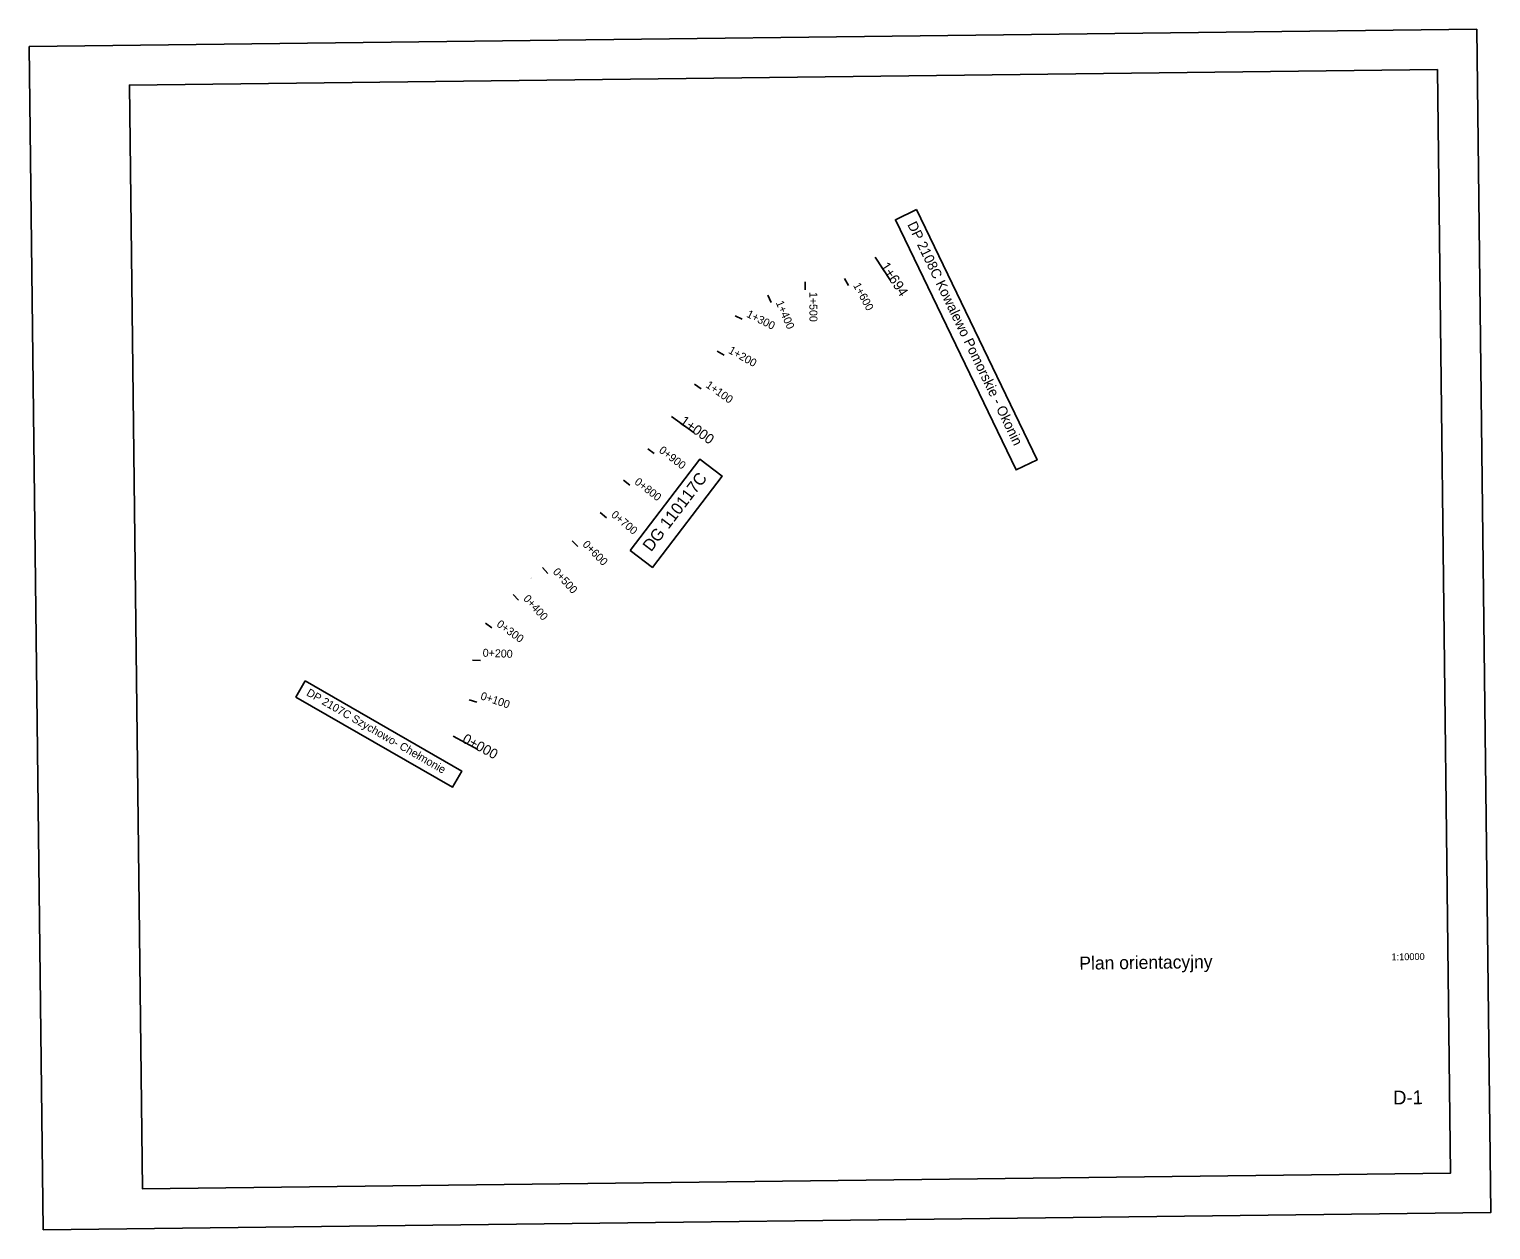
# Model space of a CAD drawing. Extents: x 6558557 to 6562223, y 5886898 to 5889911.
import ezdxf

# ---------------------------------------------------------------- set-up
doc = ezdxf.new("R2010")
doc.units = 0
for name, color, linetype in [('.opisy', 7, 'Continuous'), ('DRAFT_opis', 7, 'Continuous'), ('Level 1', 7, 'Continuous'), ('opis', 7, 'Continuous'), ('Plan proj opisy km', 7, 'Continuous')]:
    doc.layers.add(name, color=color, linetype=linetype)

msp = doc.modelspace()

# ---------------------------------------------------------------- linework, layer by layer
at = {"layer": '.opisy'}
for points in [[(6558557.1, 5889867.8), (6562188.2, 5889910.8), (6562223.3, 5886941), (6558592.3, 5886898)], [(6562089.4, 5889809.6), (6562122.1, 5887039.8), (6558841.1, 5887000.9), (6558808.3, 5889770.7)]]:
    msp.add_lwpolyline(points, close=True, dxfattribs=at)
at = {"layer": 'DRAFT_opis'}
for points in [[(6560782.6, 5889458), (6561085.3, 5888830), (6561032.8, 5888804.7), (6560730.1, 5889432.7)], [(6560064.7, 5888602.4), (6560239.5, 5888831.9), (6560295.1, 5888789.5), (6560120.4, 5888560.1)], [(6559249.3, 5888275.2), (6559642, 5888049), (6559618.7, 5888008.6), (6559226, 5888234.8)]]:
    msp.add_lwpolyline(points, close=True, dxfattribs=at)
at = {"layer": 'Plan proj opisy km'}
for points in [[(6560717.9, 5889279.9), (6560679.5, 5889338.4)], [(6560717.9, 5889279.9), (6560679.5, 5889338.4)], [(6560503.9, 5889256.5), (6560503.8, 5889276.5)], [(6560611.9, 5889267.8), (6560602.3, 5889285.4)], [(6560418.2, 5889225.1), (6560410.2, 5889243.4)], [(6560345.5, 5889182.9), (6560327.6, 5889191.8)], [(6560300, 5889092.8), (6560282.5, 5889102.6)], [(6560242.4, 5889008.5), (6560226.1, 5889020.1)], [(6560225.4, 5888898), (6560168.3, 5888938.5)], [(6560124.9, 5888845.7), (6560109.1, 5888857.9)], [(6560063.6, 5888766.6), (6560047.8, 5888778.9)], [(6560004.8, 5888684.9), (6559989.4, 5888697.7)], [(6559932.9, 5888612.7), (6559918.8, 5888626.9)], [(6559858.3, 5888544.8), (6559844.9, 5888559.6)], [(6559784.4, 5888477.6), (6559770.9, 5888492.3)], [(6559717.8, 5888408.7), (6559701.6, 5888420.4)], [(6559688.9, 5888326.4), (6559668.9, 5888327.3)], [(6559679.6, 5888221.8), (6559660.6, 5888228.1)], [(6559682.3, 5888103.3), (6559620.7, 5888136.5)]]:
    msp.add_lwpolyline(points, dxfattribs=at)

# ---------------------------------------------------------------- texts
at = {"layer": 'DRAFT_opis'}
for s, height, rotation, p in [('DP 2108C Kowalewo Pomorskie - Okonin', 25, 295.7272, (6560759.3, 5889420.8)), ('DG 110117C', 30, 52.7024, (6560117.2, 5888597.7)), ('DP 2107C Szychowo- Chełmonie', 20, 330.0518, (6559250.7, 5888240.1))]:
    msp.add_text(s, height=height, rotation=rotation, dxfattribs=at).set_placement(p)
at = {"layer": 'Level 1'}
msp.add_text('Plan orientacyjny', height=32.801, rotation=0.6782, dxfattribs=at).set_placement((6561191.5, 5887550.7))
at = {"layer": 'opis'}
for s, height, rotation, p in [('D-2.1', 1.73, 69.9171, (6559816.8, 5888530.7)), ('1:10000', 17.25, 0.6782, (6561974.3, 5887574.1)), ('D-1', 34.64, 0.6782, (6561978.5, 5887212.4))]:
    msp.add_text(s, height=height, rotation=rotation, dxfattribs=at).set_placement(p)
at = {"layer": 'Plan proj opisy km'}
for s, height, rotation, p in [('1+694', 25, 303.3359, (6560691.1, 5889316.1)), ('1+694', 25, 303.3359, (6560691.1, 5889316.1)), ('1+600', 20, 298.5857, (6560623.1, 5889268.2)), ('1+500', 20, 270.3114, (6560513.9, 5889251.5)), ('1+300', 20, 333.3815, (6560354.5, 5889189.6)), ('1+400', 20, 293.6597, (6560429.4, 5889224.6)), ('1+200', 20, 330.6948, (6560309.2, 5889099.1)), ('1+100', 20, 324.6756, (6560252.3, 5889013.8)), ('1+000', 25, 324.6756, (6560187.2, 5888922)), ('0+900', 20, 322.4963, (6560135, 5888850.6)), ('0+800', 20, 322.1153, (6560073.7, 5888771.4)), ('0+700', 20, 320.02, (6560015, 5888689.3)), ('0+600', 20, 314.7041, (6559943.5, 5888616.2)), ('0+500', 20, 312.2946, (6559869.1, 5888547.9)), ('0+400', 20, 312.2946, (6559795.1, 5888480.6)), ('0+300', 20, 324.0672, (6559727.7, 5888413.9)), ('0+200', 20, 357.6435, (6559694.3, 5888336.2)), ('0+100', 20, 341.4592, (6559687.5, 5888229.6)), ('0+000', 25, 331.6624, (6559641.5, 5888122.4))]:
    msp.add_text(s, height=height, rotation=rotation, dxfattribs=at).set_placement(p)

doc.saveas('drawing.dxf')
